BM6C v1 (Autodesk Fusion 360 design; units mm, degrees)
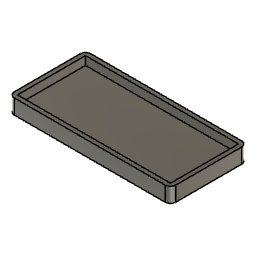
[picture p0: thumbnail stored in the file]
sketch "Sketch1" plane through (0, 0, 0) normal (0, 0, 1) x axis (1, 0, 0)
  line L1 (72, 0) -> (0, 0)
  line L2 (72, 32) -> (72, 0)
  line L3 (0, 32) -> (72, 32)
  line L4 (0, 0) -> (0, 32)
  line L5 (74, -2) -> (-2, -2)
  line L6 (74, 34) -> (74, -2)
  line L7 (-2, 34) -> (74, 34)
  line L8 (-2, -2) -> (-2, 34)
  point P1 (0, 0)
  point P2 (0, 0)
  point P3 (72, 0)
  point P5 (0, 32)
  horizontal L1
  vertical L2
  horizontal L3
  vertical L4
  coincident P1 P2
  dimension "d1" distance P2 P3 = 72
  dimension "d2" distance P2 P5 = 32
  dimension "d3" = 2
extrude "Extrude1" new body sketch "Sketch1" against normal blind 7
extrude "Extrude2" cut sketch "Sketch1" profile of L1 L2 L3 L4 against normal blind 4
fillet "Fillet1" radius 2.5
